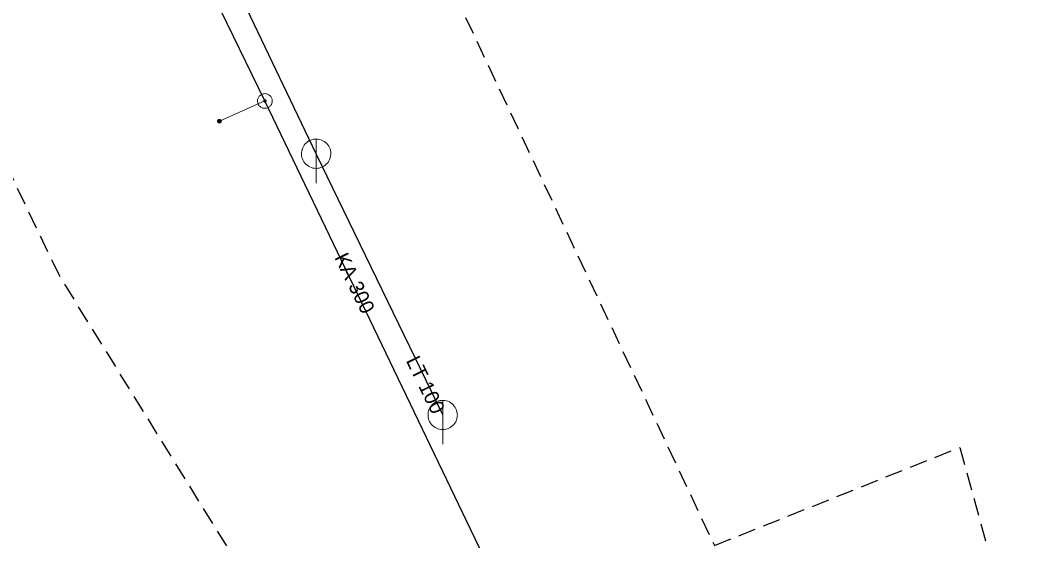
# Model space of a CAD drawing. Extents: x -688691 to -688449, y -974248 to -973966.
# Drawn here: x -688629.3 to -688559.6, y -974212.5 to -974177 of the extents above; entities that cross this region are included whole.
import ezdxf

# ---------------------------------------------------------------- set-up
doc = ezdxf.new("R2010")
doc.units = 0
doc.header["$LTSCALE"] = 0.4
doc.linetypes.add('MEDIUM_DASHED', pattern=[4.5, 3, -1.5])
for name, color, linetype, lineweight in [('1', 7, 'MEDIUM_DASHED', 25), ('14', 7, 'Continuous', 25), ('17', 7, 'Continuous', 25), ('22', 7, 'Continuous', 13), ('47', 7, 'Continuous', 13), ('9', 7, 'Continuous', 13)]:
    doc.layers.add(name, color=color, linetype=linetype, lineweight=lineweight)

msp = doc.modelspace()

# ---------------------------------------------------------------- linework, layer by layer
at = {"layer": '1'}
msp.add_lwpolyline([(-688492.642, -974007.422), (-688474.778, -973965.553), (-688449.099, -973975.602), (-688472.545, -974030.309), (-688492.642, -974033.659), (-688555.165, -974021.936), (-688650.066, -974071.061), (-688624.387, -974128.002), (-688613.222, -974120.745), (-688593.125, -974162.055), (-688604.29, -974165.404), (-688581.96, -974212.855), (-688565.213, -974206.156), (-688558.514, -974230.719), (-688607.64, -974248.024), (-688622.154, -974231.277), (-688607.64, -974225.136), (-688626.62, -974194.433), (-688691.376, -974059.338), (-688565.213, -973995.698), (-688544, -974002.397)], close=True, dxfattribs=at)
at = {"layer": '14', "lineweight": 13}
msp.add_line((-688615.708, -974183.888), (-688612.61, -974182.51), dxfattribs=at)
at = {"layer": '14'}
msp.add_lwpolyline([(-688600.487, -974203.944), (-688609.114, -974186.109), (-688615.099, -974173.573), (-688627.959, -974140.596)], dxfattribs=at)
at = {"layer": '17'}
for p, q in [((-688612.61, -974182.51), (-688622.145, -974162.896)), ((-688592.598, -974224.214), (-688612.61, -974182.51))]:
    msp.add_line(p, q, dxfattribs=at)
at = {"layer": '22'}
for p, q in [((-688609.114, -974188.109), (-688609.113, -974185.109)), ((-688600.487, -974205.944), (-688600.486, -974202.944))]:
    msp.add_line(p, q, dxfattribs=at)
for points in [[(-688608.114, -974186.109), (-688608.119, -974186), (-688608.137, -974185.892), (-688608.167, -974185.786), (-688608.207, -974185.685), (-688608.259, -974185.588), (-688608.321, -974185.498), (-688608.393, -974185.415), (-688608.473, -974185.341), (-688608.561, -974185.275), (-688608.655, -974185.22), (-688608.755, -974185.175), (-688608.86, -974185.142), (-688608.967, -974185.12), (-688609.076, -974185.11), (-688609.186, -974185.112), (-688609.294, -974185.126), (-688609.401, -974185.151), (-688609.504, -974185.188), (-688609.602, -974185.237), (-688609.694, -974185.295), (-688609.78, -974185.364), (-688609.857, -974185.441), (-688609.926, -974185.527), (-688609.985, -974185.619), (-688610.033, -974185.717), (-688610.07, -974185.82), (-688610.096, -974185.927), (-688610.11, -974186.035), (-688610.113, -974186.145), (-688610.103, -974186.254), (-688610.082, -974186.361), (-688610.048, -974186.465), (-688610.004, -974186.565), (-688609.949, -974186.66), (-688609.883, -974186.748), (-688609.809, -974186.828), (-688609.726, -974186.9), (-688609.636, -974186.962), (-688609.54, -974187.014), (-688609.438, -974187.055), (-688609.333, -974187.085), (-688609.225, -974187.103), (-688609.115, -974187.109), (-688609.006, -974187.103), (-688608.898, -974187.085), (-688608.793, -974187.056), (-688608.691, -974187.015), (-688608.594, -974186.963), (-688608.504, -974186.901), (-688608.421, -974186.83), (-688608.346, -974186.75), (-688608.281, -974186.662), (-688608.225, -974186.568), (-688608.181, -974186.468), (-688608.147, -974186.364), (-688608.125, -974186.256), (-688608.115, -974186.147)], [(-688599.487, -974203.944), (-688599.492, -974203.835), (-688599.51, -974203.727), (-688599.54, -974203.621), (-688599.58, -974203.52), (-688599.632, -974203.423), (-688599.694, -974203.333), (-688599.766, -974203.25), (-688599.846, -974203.176), (-688599.934, -974203.11), (-688600.028, -974203.055), (-688600.128, -974203.01), (-688600.233, -974202.977), (-688600.34, -974202.955), (-688600.449, -974202.945), (-688600.559, -974202.947), (-688600.667, -974202.961), (-688600.774, -974202.986), (-688600.877, -974203.023), (-688600.975, -974203.072), (-688601.067, -974203.13), (-688601.153, -974203.199), (-688601.23, -974203.276), (-688601.299, -974203.362), (-688601.358, -974203.454), (-688601.406, -974203.552), (-688601.443, -974203.655), (-688601.469, -974203.762), (-688601.483, -974203.87), (-688601.486, -974203.98), (-688601.476, -974204.089), (-688601.455, -974204.196), (-688601.421, -974204.3), (-688601.377, -974204.4), (-688601.322, -974204.495), (-688601.256, -974204.583), (-688601.182, -974204.663), (-688601.099, -974204.735), (-688601.009, -974204.797), (-688600.913, -974204.849), (-688600.811, -974204.89), (-688600.706, -974204.92), (-688600.598, -974204.938), (-688600.488, -974204.944), (-688600.379, -974204.938), (-688600.271, -974204.92), (-688600.166, -974204.891), (-688600.064, -974204.85), (-688599.967, -974204.798), (-688599.877, -974204.736), (-688599.794, -974204.665), (-688599.719, -974204.585), (-688599.654, -974204.497), (-688599.598, -974204.403), (-688599.554, -974204.303), (-688599.52, -974204.199), (-688599.498, -974204.091), (-688599.488, -974203.982)]]:
    msp.add_lwpolyline(points, close=True, dxfattribs=at)
at = {"layer": '47'}
for points in [[(-688612.391, -974182.959), (-688612.345, -974182.934), (-688612.302, -974182.904), (-688612.263, -974182.869), (-688612.227, -974182.832), (-688612.195, -974182.79), (-688612.168, -974182.744), (-688612.147, -974182.697), (-688612.13, -974182.648), (-688612.118, -974182.597), (-688612.111, -974182.545), (-688612.11, -974182.492), (-688612.115, -974182.44), (-688612.124, -974182.389), (-688612.14, -974182.339), (-688612.16, -974182.291), (-688612.185, -974182.245), (-688612.215, -974182.202), (-688612.25, -974182.162), (-688612.287, -974182.127), (-688612.329, -974182.095), (-688612.375, -974182.068), (-688612.422, -974182.046), (-688612.472, -974182.029), (-688612.522, -974182.017), (-688612.574, -974182.011), (-688612.627, -974182.01), (-688612.679, -974182.014), (-688612.73, -974182.024), (-688612.78, -974182.04), (-688612.828, -974182.06), (-688612.874, -974182.085), (-688612.917, -974182.115), (-688612.957, -974182.149), (-688612.992, -974182.187), (-688613.024, -974182.229), (-688613.051, -974182.274), (-688613.073, -974182.321), (-688613.091, -974182.371), (-688613.102, -974182.422), (-688613.108, -974182.474), (-688613.109, -974182.527), (-688613.105, -974182.578), (-688613.095, -974182.63), (-688613.079, -974182.68), (-688613.059, -974182.728), (-688613.034, -974182.774), (-688613.004, -974182.817), (-688612.97, -974182.856), (-688612.932, -974182.892), (-688612.89, -974182.924), (-688612.845, -974182.951), (-688612.798, -974182.973), (-688612.749, -974182.99), (-688612.697, -974183.001), (-688612.645, -974183.008), (-688612.592, -974183.009), (-688612.541, -974183.004), (-688612.489, -974182.995), (-688612.439, -974182.979)], [(-688612.574, -974182.583), (-688612.566, -974182.579), (-688612.559, -974182.574), (-688612.553, -974182.569), (-688612.547, -974182.563), (-688612.542, -974182.555), (-688612.537, -974182.548), (-688612.533, -974182.54), (-688612.531, -974182.532), (-688612.529, -974182.524), (-688612.528, -974182.515), (-688612.528, -974182.506), (-688612.528, -974182.498), (-688612.53, -974182.49), (-688612.532, -974182.482), (-688612.536, -974182.474), (-688612.54, -974182.466), (-688612.545, -974182.459), (-688612.55, -974182.453), (-688612.556, -974182.447), (-688612.564, -974182.442), (-688612.571, -974182.437), (-688612.579, -974182.433), (-688612.587, -974182.431), (-688612.596, -974182.428), (-688612.604, -974182.428), (-688612.613, -974182.428), (-688612.621, -974182.428), (-688612.629, -974182.43), (-688612.637, -974182.432), (-688612.645, -974182.436), (-688612.653, -974182.44), (-688612.66, -974182.445), (-688612.666, -974182.45), (-688612.672, -974182.456), (-688612.677, -974182.464), (-688612.682, -974182.47), (-688612.686, -974182.479), (-688612.688, -974182.487), (-688612.691, -974182.496), (-688612.691, -974182.504), (-688612.691, -974182.513), (-688612.691, -974182.521), (-688612.689, -974182.529), (-688612.687, -974182.537), (-688612.683, -974182.545), (-688612.679, -974182.553), (-688612.674, -974182.56), (-688612.669, -974182.566), (-688612.663, -974182.572), (-688612.655, -974182.577), (-688612.649, -974182.582), (-688612.64, -974182.586), (-688612.632, -974182.588), (-688612.624, -974182.59), (-688612.615, -974182.591), (-688612.606, -974182.591), (-688612.598, -974182.591), (-688612.59, -974182.589), (-688612.582, -974182.587)]]:
    msp.add_lwpolyline(points, close=True, dxfattribs=at)
at = {"layer": '9'}
for points in [[(-688615.834, -974183.888), (-688615.834, -974183.901), (-688615.831, -974183.914), (-688615.829, -974183.927), (-688615.824, -974183.939), (-688615.818, -974183.951), (-688615.811, -974183.962), (-688615.803, -974183.972), (-688615.793, -974183.982), (-688615.782, -974183.99), (-688615.772, -974183.997), (-688615.76, -974184.003), (-688615.748, -974184.008), (-688615.735, -974184.011), (-688615.722, -974184.013), (-688615.709, -974184.015), (-688615.696, -974184.014), (-688615.683, -974184.012), (-688615.67, -974184.009), (-688615.657, -974184.004), (-688615.646, -974183.998), (-688615.635, -974183.991), (-688615.625, -974183.983), (-688615.615, -974183.973), (-688615.607, -974183.963), (-688615.6, -974183.952), (-688615.594, -974183.94), (-688615.589, -974183.928), (-688615.586, -974183.915), (-688615.584, -974183.902), (-688615.581, -974183.889), (-688615.583, -974183.876), (-688615.585, -974183.863), (-688615.588, -974183.85), (-688615.593, -974183.838), (-688615.598, -974183.826), (-688615.606, -974183.815), (-688615.614, -974183.805), (-688615.624, -974183.795), (-688615.634, -974183.787), (-688615.645, -974183.78), (-688615.657, -974183.774), (-688615.669, -974183.769), (-688615.682, -974183.766), (-688615.695, -974183.764), (-688615.708, -974183.763), (-688615.721, -974183.763), (-688615.733, -974183.765), (-688615.747, -974183.768), (-688615.759, -974183.773), (-688615.771, -974183.779), (-688615.782, -974183.786), (-688615.792, -974183.794), (-688615.802, -974183.804), (-688615.809, -974183.814), (-688615.817, -974183.825), (-688615.823, -974183.837), (-688615.828, -974183.849), (-688615.831, -974183.862), (-688615.833, -974183.875)], [(-688615.814, -974183.888), (-688615.815, -974183.899), (-688615.813, -974183.91), (-688615.809, -974183.921), (-688615.806, -974183.931), (-688615.801, -974183.941), (-688615.795, -974183.95), (-688615.788, -974183.959), (-688615.78, -974183.967), (-688615.771, -974183.974), (-688615.762, -974183.98), (-688615.752, -974183.985), (-688615.742, -974183.989), (-688615.731, -974183.992), (-688615.72, -974183.995), (-688615.709, -974183.995), (-688615.698, -974183.995), (-688615.687, -974183.993), (-688615.676, -974183.99), (-688615.666, -974183.986), (-688615.656, -974183.981), (-688615.647, -974183.975), (-688615.638, -974183.968), (-688615.63, -974183.96), (-688615.623, -974183.951), (-688615.617, -974183.942), (-688615.612, -974183.932), (-688615.608, -974183.922), (-688615.605, -974183.911), (-688615.603, -974183.9), (-688615.602, -974183.889), (-688615.602, -974183.878), (-688615.603, -974183.867), (-688615.607, -974183.856), (-688615.611, -974183.846), (-688615.616, -974183.836), (-688615.622, -974183.827), (-688615.629, -974183.818), (-688615.637, -974183.81), (-688615.646, -974183.803), (-688615.655, -974183.797), (-688615.665, -974183.792), (-688615.674, -974183.788), (-688615.686, -974183.785), (-688615.696, -974183.783), (-688615.708, -974183.783), (-688615.719, -974183.782), (-688615.73, -974183.784), (-688615.741, -974183.787), (-688615.75, -974183.791), (-688615.761, -974183.796), (-688615.77, -974183.802), (-688615.779, -974183.809), (-688615.787, -974183.817), (-688615.794, -974183.826), (-688615.799, -974183.835), (-688615.804, -974183.845), (-688615.809, -974183.855), (-688615.812, -974183.866), (-688615.814, -974183.877)], [(-688615.795, -974183.888), (-688615.795, -974183.897), (-688615.794, -974183.906), (-688615.791, -974183.915), (-688615.788, -974183.923), (-688615.784, -974183.931), (-688615.779, -974183.939), (-688615.772, -974183.946), (-688615.767, -974183.952), (-688615.76, -974183.958), (-688615.752, -974183.963), (-688615.744, -974183.967), (-688615.736, -974183.97), (-688615.727, -974183.973), (-688615.718, -974183.974), (-688615.709, -974183.976), (-688615.7, -974183.975), (-688615.691, -974183.974), (-688615.682, -974183.971), (-688615.674, -974183.968), (-688615.666, -974183.964), (-688615.657, -974183.959), (-688615.651, -974183.953), (-688615.645, -974183.947), (-688615.639, -974183.94), (-688615.634, -974183.932), (-688615.63, -974183.924), (-688615.627, -974183.916), (-688615.624, -974183.907), (-688615.623, -974183.898), (-688615.62, -974183.889), (-688615.622, -974183.88), (-688615.623, -974183.871), (-688615.625, -974183.862), (-688615.629, -974183.854), (-688615.633, -974183.846), (-688615.638, -974183.838), (-688615.644, -974183.831), (-688615.65, -974183.825), (-688615.657, -974183.819), (-688615.665, -974183.814), (-688615.673, -974183.81), (-688615.681, -974183.807), (-688615.69, -974183.804), (-688615.699, -974183.803), (-688615.708, -974183.802), (-688615.717, -974183.802), (-688615.726, -974183.803), (-688615.735, -974183.806), (-688615.743, -974183.809), (-688615.75, -974183.813), (-688615.759, -974183.818), (-688615.766, -974183.824), (-688615.772, -974183.83), (-688615.777, -974183.837), (-688615.782, -974183.845), (-688615.787, -974183.853), (-688615.79, -974183.861), (-688615.793, -974183.87), (-688615.794, -974183.879)], [(-688615.775, -974183.888), (-688615.775, -974183.895), (-688615.774, -974183.902), (-688615.772, -974183.909), (-688615.77, -974183.915), (-688615.767, -974183.921), (-688615.763, -974183.927), (-688615.759, -974183.933), (-688615.754, -974183.938), (-688615.748, -974183.942), (-688615.742, -974183.946), (-688615.736, -974183.949), (-688615.73, -974183.952), (-688615.723, -974183.953), (-688615.716, -974183.956), (-688615.709, -974183.956), (-688615.701, -974183.956), (-688615.695, -974183.954), (-688615.688, -974183.953), (-688615.682, -974183.95), (-688615.674, -974183.947), (-688615.67, -974183.943), (-688615.664, -974183.939), (-688615.659, -974183.934), (-688615.655, -974183.928), (-688615.651, -974183.922), (-688615.647, -974183.916), (-688615.645, -974183.91), (-688615.643, -974183.903), (-688615.642, -974183.896), (-688615.641, -974183.889), (-688615.641, -974183.882), (-688615.642, -974183.875), (-688615.644, -974183.868), (-688615.647, -974183.862), (-688615.65, -974183.855), (-688615.654, -974183.85), (-688615.657, -974183.844), (-688615.663, -974183.839), (-688615.669, -974183.835), (-688615.674, -974183.831), (-688615.681, -974183.828), (-688615.687, -974183.825), (-688615.694, -974183.823), (-688615.701, -974183.822), (-688615.708, -974183.822), (-688615.715, -974183.822), (-688615.722, -974183.822), (-688615.728, -974183.824), (-688615.735, -974183.827), (-688615.741, -974183.83), (-688615.747, -974183.834), (-688615.753, -974183.838), (-688615.758, -974183.843), (-688615.762, -974183.849), (-688615.766, -974183.854), (-688615.769, -974183.861), (-688615.772, -974183.867), (-688615.772, -974183.874), (-688615.775, -974183.881)], [(-688615.755, -974183.888), (-688615.755, -974183.893), (-688615.755, -974183.898), (-688615.754, -974183.903), (-688615.752, -974183.907), (-688615.75, -974183.912), (-688615.747, -974183.916), (-688615.744, -974183.919), (-688615.74, -974183.923), (-688615.737, -974183.926), (-688615.733, -974183.929), (-688615.728, -974183.931), (-688615.723, -974183.933), (-688615.719, -974183.934), (-688615.714, -974183.936), (-688615.709, -974183.936), (-688615.704, -974183.936), (-688615.699, -974183.935), (-688615.694, -974183.934), (-688615.69, -974183.932), (-688615.684, -974183.93), (-688615.681, -974183.927), (-688615.677, -974183.924), (-688615.674, -974183.92), (-688615.671, -974183.917), (-688615.668, -974183.913), (-688615.666, -974183.908), (-688615.664, -974183.904), (-688615.663, -974183.899), (-688615.662, -974183.894), (-688615.661, -974183.889), (-688615.661, -974183.884), (-688615.662, -974183.879), (-688615.663, -974183.874), (-688615.665, -974183.87), (-688615.667, -974183.865), (-688615.67, -974183.861), (-688615.673, -974183.857), (-688615.676, -974183.854), (-688615.679, -974183.851), (-688615.684, -974183.848), (-688615.689, -974183.846), (-688615.693, -974183.844), (-688615.698, -974183.843), (-688615.703, -974183.842), (-688615.708, -974183.842), (-688615.713, -974183.842), (-688615.718, -974183.843), (-688615.723, -974183.843), (-688615.727, -974183.845), (-688615.732, -974183.847), (-688615.736, -974183.85), (-688615.739, -974183.853), (-688615.743, -974183.856), (-688615.745, -974183.86), (-688615.749, -974183.864), (-688615.75, -974183.869), (-688615.753, -974183.873), (-688615.754, -974183.878), (-688615.755, -974183.883)], [(-688615.735, -974183.888), (-688615.735, -974183.891), (-688615.736, -974183.894), (-688615.735, -974183.896), (-688615.733, -974183.899), (-688615.733, -974183.902), (-688615.731, -974183.904), (-688615.728, -974183.906), (-688615.727, -974183.908), (-688615.725, -974183.91), (-688615.723, -974183.912), (-688615.72, -974183.914), (-688615.717, -974183.915), (-688615.715, -974183.915), (-688615.712, -974183.916), (-688615.709, -974183.916), (-688615.706, -974183.916), (-688615.703, -974183.916), (-688615.7, -974183.915), (-688615.698, -974183.914), (-688615.695, -974183.913), (-688615.693, -974183.911), (-688615.69, -974183.909), (-688615.688, -974183.907), (-688615.687, -974183.905), (-688615.684, -974183.903), (-688615.684, -974183.9), (-688615.682, -974183.897), (-688615.682, -974183.895), (-688615.681, -974183.892), (-688615.679, -974183.889), (-688615.681, -974183.886), (-688615.681, -974183.883), (-688615.682, -974183.88), (-688615.683, -974183.878), (-688615.684, -974183.875), (-688615.686, -974183.873), (-688615.687, -974183.87), (-688615.689, -974183.868), (-688615.692, -974183.867), (-688615.694, -974183.865), (-688615.696, -974183.864), (-688615.699, -974183.863), (-688615.701, -974183.862), (-688615.705, -974183.862), (-688615.708, -974183.861), (-688615.711, -974183.862), (-688615.714, -974183.861), (-688615.716, -974183.863), (-688615.719, -974183.863), (-688615.722, -974183.864), (-688615.723, -974183.866), (-688615.726, -974183.867), (-688615.728, -974183.869), (-688615.73, -974183.872), (-688615.732, -974183.874), (-688615.733, -974183.877), (-688615.733, -974183.879), (-688615.735, -974183.882), (-688615.735, -974183.885)], [(-688615.716, -974183.888), (-688615.716, -974183.89), (-688615.716, -974183.89), (-688615.715, -974183.89), (-688615.715, -974183.892), (-688615.716, -974183.893), (-688615.714, -974183.893), (-688615.714, -974183.893), (-688615.714, -974183.895), (-688615.714, -974183.895), (-688615.713, -974183.896), (-688615.711, -974183.896), (-688615.711, -974183.896), (-688615.711, -974183.897), (-688615.709, -974183.897), (-688615.709, -974183.897), (-688615.708, -974183.897), (-688615.706, -974183.897), (-688615.706, -974183.896), (-688615.706, -974183.896), (-688615.704, -974183.896), (-688615.704, -974183.895), (-688615.704, -974183.895), (-688615.703, -974183.894), (-688615.703, -974183.894), (-688615.701, -974183.893), (-688615.701, -974183.892), (-688615.7, -974183.891), (-688615.7, -974183.891), (-688615.7, -974183.89), (-688615.7, -974183.889), (-688615.7, -974183.888), (-688615.7, -974183.887), (-688615.7, -974183.887), (-688615.701, -974183.886), (-688615.701, -974183.885), (-688615.701, -974183.884), (-688615.701, -974183.884), (-688615.703, -974183.883), (-688615.703, -974183.883), (-688615.704, -974183.882), (-688615.705, -974183.882), (-688615.706, -974183.881), (-688615.706, -974183.881), (-688615.706, -974183.881), (-688615.708, -974183.881), (-688615.709, -974183.881), (-688615.71, -974183.881), (-688615.71, -974183.881), (-688615.711, -974183.882), (-688615.712, -974183.881), (-688615.713, -974183.883), (-688615.713, -974183.883), (-688615.714, -974183.883), (-688615.714, -974183.883), (-688615.715, -974183.885), (-688615.715, -974183.886), (-688615.715, -974183.887), (-688615.716, -974183.887), (-688615.716, -974183.888)]]:
    msp.add_lwpolyline(points, close=True, dxfattribs=at)

# ---------------------------------------------------------------- texts
at = {"layer": '1'}
for s, p in [('KA 300', (-688607.894, -974193.191)), ('LT 100', (-688603.013, -974200.23))]:
    msp.add_text(s, height=1, rotation=296, dxfattribs=at).set_placement(p)

doc.saveas('drawing.dxf')
